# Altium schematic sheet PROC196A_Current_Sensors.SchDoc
size 431 x 279 mm; Date: Not shown in title block; ApprovedBy: Not shown in title block; CheckedBy: Not shown in title block; Author: Not shown in title block; CompanyName: Not shown in title block; Engineer: Not shown in title block; Organization: Not shown in title block; Address1: Not shown in title block; Address2: Not shown in title block; Address3: Not shown in title block; Address4: Not shown in title block; DocumentNumber: 23; Revision: Use project parameter SCH_Rev; SheetNumber: 23; SheetTotal: 25; PageSetup: Record=PageOptions¦CenterHorizontal=True¦CenterVertical=True¦PrintScale=1.00¦XCorrection=1.00¦YCorrection=1.00¦PrintKind=0¦BorderSize=5000000¦LeftOffset=0¦BottomOffset=0¦Orientation=2¦PaperLength=1000¦PaperWidth=1000¦Scale=100¦PaperSource=15¦PrintQuality=600¦MediaType=1¦DitherType=10¦PaperKind=Letter¦PrintScaleMode=1
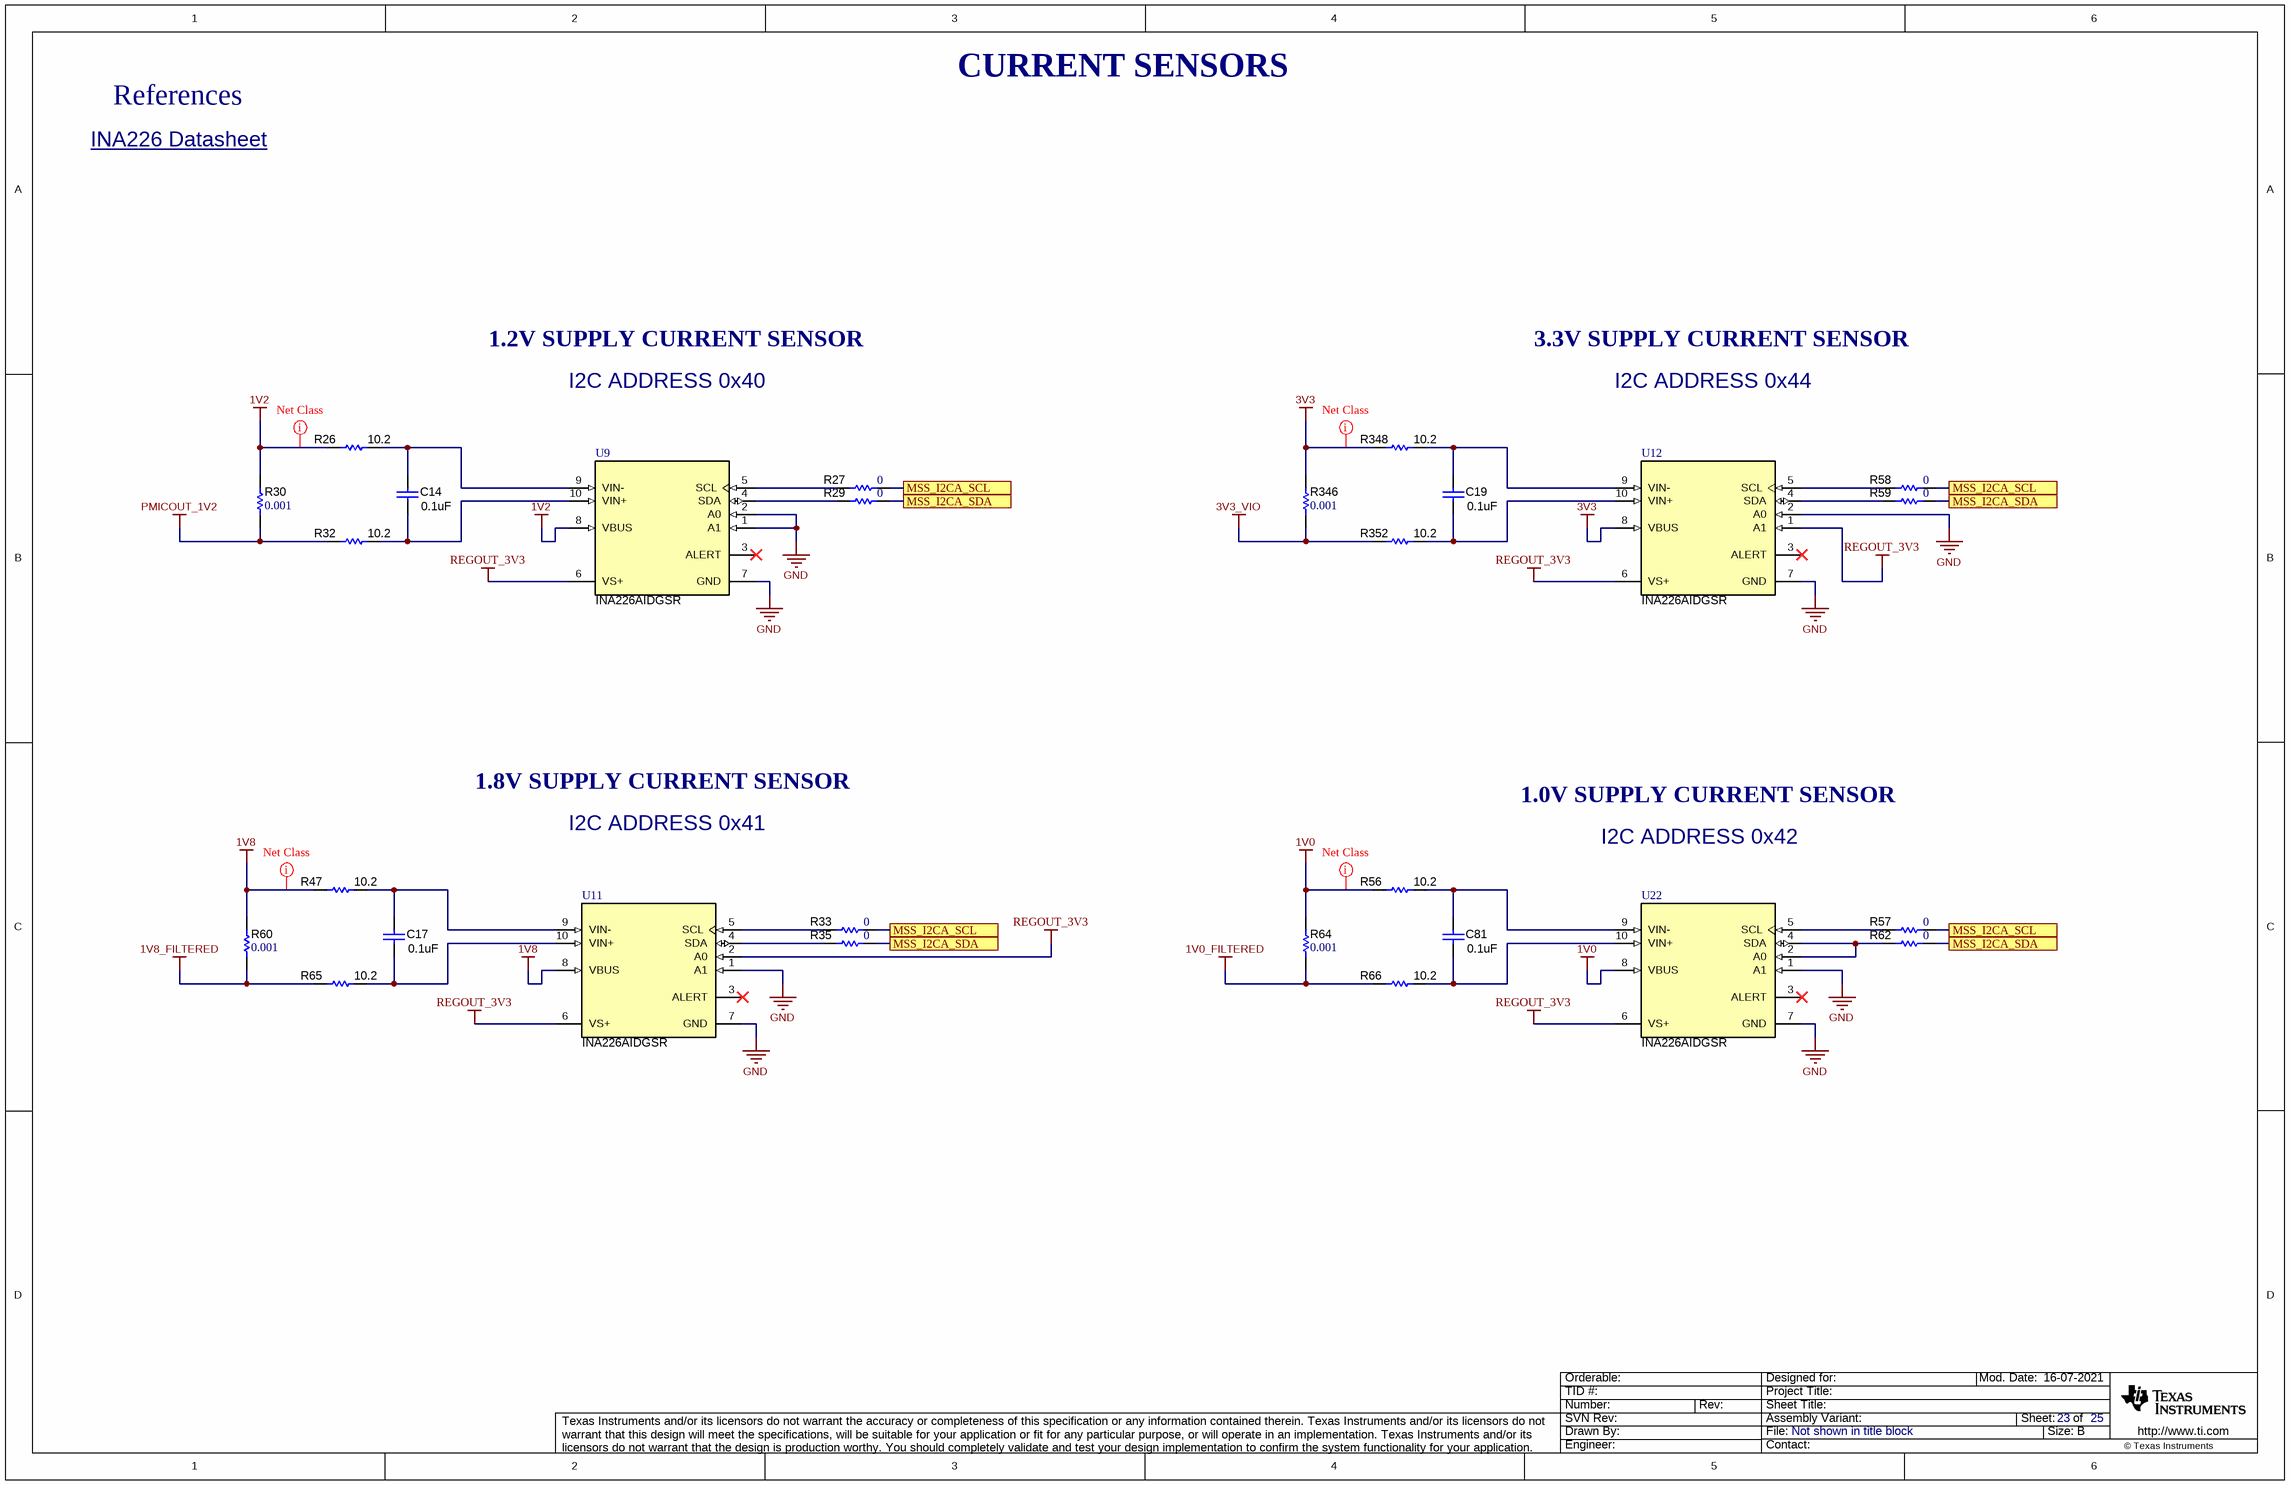
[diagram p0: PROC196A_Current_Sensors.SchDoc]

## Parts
C14  ValueDisplayed: 0.1uF  [0402L]  (hidden comment: GCM155R71A104KA55D)
C17  ValueDisplayed: 0.1uF  [0402L]  (hidden comment: GCM155R71A104KA55D)
C19  ValueDisplayed: 0.1uF  [0402L]  (hidden comment: GCM155R71A104KA55D)
C81  ValueDisplayed: 0.1uF  [0402L]  (hidden comment: GCM155R71A104KA55D)
R26  ValueDisplayed: 10.2  [0402L]  (hidden comment: CRCW040210R2FKED)
R27  ValueDisplayed: 0  [0402L]  (hidden comment: ERJ-2GE0R00X)
R29  ValueDisplayed: 0  [0402L]  (hidden comment: ERJ-2GE0R00X)
R30  ValueDisplayed: 0.001  [1206L]  (hidden comment: CSNL1206FT1L00)
R32  ValueDisplayed: 10.2  [0402L]  (hidden comment: CRCW040210R2FKED)
R33  ValueDisplayed: 0  [0402L]  (hidden comment: ERJ-2GE0R00X)
R35  ValueDisplayed: 0  [0402L]  (hidden comment: ERJ-2GE0R00X)
R47  ValueDisplayed: 10.2  [0402L]  (hidden comment: CRCW040210R2FKED)
R56  ValueDisplayed: 10.2  [0402L]  (hidden comment: CRCW040210R2FKED)
R57  ValueDisplayed: 0  [0402L]  (hidden comment: ERJ-2GE0R00X)
R58  ValueDisplayed: 0  [0402L]  (hidden comment: ERJ-2GE0R00X)
R59  ValueDisplayed: 0  [0402L]  (hidden comment: ERJ-2GE0R00X)
R60  ValueDisplayed: 0.001  [1206L]  (hidden comment: CSNL1206FT1L00)
R62  ValueDisplayed: 0  [0402L]  (hidden comment: ERJ-2GE0R00X)
R64  ValueDisplayed: 0.001  [1206L]  (hidden comment: CSNL1206FT1L00)
R65  ValueDisplayed: 10.2  [0402L]  (hidden comment: CRCW040210R2FKED)
R66  ValueDisplayed: 10.2  [0402L]  (hidden comment: CRCW040210R2FKED)
R346  ValueDisplayed: 0.001  [1206L]  (hidden comment: CSNL1206FT1L00)
R348  ValueDisplayed: 10.2  [0402L]  (hidden comment: CRCW040210R2FKED)
R352  ValueDisplayed: 10.2  [0402L]  (hidden comment: CRCW040210R2FKED)
U9  INA226AIDGSR  [DGS0010A_L]
U11  INA226AIDGSR  [DGS0010A_L]
U12  INA226AIDGSR  [DGS0010A_L]
U22  INA226AIDGSR  [DGS0010A_L]

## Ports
MSS_I2CA_SCL, MSS_I2CA_SDA

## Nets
1V0: R56.1 R64.2 U22.8(VBUS)
1V0_FILTERED: R64.1 R66.1
1V2: R26.1 R30.2 U9.8(VBUS)
1V8: R47.1 R60.2 U11.8(VBUS)
1V8_FILTERED: R60.1 R65.1
3V3: R346.2 R348.1 U12.8(VBUS)
3V3_VIO: R346.1 R352.1
GND: U9.1(A1) U9.2(A0) U9.7(GND) U11.1(A1) U11.7(GND) U12.2(A0) U12.7(GND) U22.1(A1) U22.7(GND)
PMICOUT_1V2: R30.1 R32.1
REGOUT_3V3: U9.6(VS+) U11.2(A0) U11.6(VS+) U12.1(A1) U12.6(VS+) U22.6(VS+)
MSS_I2CA_SCL: R27.2 R33.2 R57.2 R58.2 ; port MSS_I2CA_SCL
MSS_I2CA_SDA: R29.2 R35.2 R59.2 R62.2 ; port MSS_I2CA_SDA
NetC14_1: C14.1 R26.2 U9.9(VIN-)
NetC14_2: C14.2 R32.2 U9.10(VIN+)
NetC17_1: C17.1 R47.2 U11.9(VIN-)
NetC17_2: C17.2 R65.2 U11.10(VIN+)
NetC19_1: C19.1 R348.2 U12.9(VIN-)
NetC19_2: C19.2 R352.2 U12.10(VIN+)
NetC81_1: C81.1 R56.2 U22.9(VIN-)
NetC81_2: C81.2 R66.2 U22.10(VIN+)
NetR27_1: R27.1 U9.5(SCL)
NetR29_1: R29.1 U9.4(SDA)
NetR33_1: R33.1 U11.5(SCL)
NetR35_1: R35.1 U11.4(SDA)
NetR57_1: R57.1 U22.5(SCL)
NetR58_1: R58.1 U12.5(SCL)
NetR59_1: R59.1 U12.4(SDA)
NetR62_1: R62.1 U22.2(A0) U22.4(SDA)

Not connected (* = marked no-connect by the designer): U9 3(ALERT)*; U11 3(ALERT)*; U12 3(ALERT)*; U22 3(ALERT)*

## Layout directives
net class PWR: 1V0, 1V2, 1V8, 3V3

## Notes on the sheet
- CURRENT SENSORS
- References
- INA226 Datasheet <http://www.ti.com/lit/ds/symlink/ina226.pdf>
- 1.2V SUPPLY CURRENT SENSOR
- 3.3V SUPPLY CURRENT SENSOR
- I2C ADDRESS 0x40
- I2C ADDRESS 0x44
- 1.8V SUPPLY CURRENT SENSOR
- I2C ADDRESS 0x41
- 1.0V SUPPLY CURRENT SENSOR
- I2C ADDRESS 0x42

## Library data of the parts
C14 C17 C19 C81 = CMP-0006350-2: CAP, CERM, 0.1 uF, 10 V, +/- 10%, X7R, AEC-Q200 Grade 1, 0402; Manufacturer: MuRata; TaMin_C: -55°C; Polarized: N; SizeAreaWB_mm2: 3; Value1: Unknown; U/M: EA; Value: 0.1uF; TaMax_C: 125°C; SizeZ_mm: 0.6; SizeX_mm: 1; SizeY_mm: 0.5; Cap_Case: 0402; Value2: 10V; AEC Qualified: Y; Cap_F: 100nF; AEC Category: Q200
R26 R32 R47 R56 R65 R66 R348 R352 = CMP-0025964-3: RES, 10.2, 1%, 0.063 W, AEC-Q200 Grade 0, 0402; Manufacturer: Vishay-Dale; Power_W: 63mW; TempCo: 100 ppm/C; Value_Code: 10R2; Value: 10.2; EIA_Code: E96; SizeX_mm: 1; SizeY_mm: 0.5; SizeZ_mm: 0.6; Value2: 0.063W; AEC Qualified: Y; VDC_V: 50V; AEC Category: Q200; AEC Grade: 0
R27 R29 R33 R35 R57-R59 R62 = CMP-0026992-3: RES, 0, 5%, 0.1 W, AEC-Q200 Grade 0, 0402; Manufacturer: Panasonic; Power_W: 100mW; TempCo: 600 ppm/C; Value_Code: 0000; Value: 0; EIA_Code: E24; SizeX_mm: 1; SizeY_mm: 0.5; SizeZ_mm: 0.6; Value2: 0.1W; AEC Qualified: Y; VDC_V: 50V; AEC Category: Q200; SizeAreaWB_mm2: 3
R30 R60 R64 R346 = CMP-0017253-2: RES, 0.001, 1%, 1 W, AEC-Q200 Grade 0, 1206; Manufacturer: Stackpole Electronics Inc; Power_W: 1W; TempCo: 50 ppm/C; Value_Code: 1L000; U/M: EA; Value: 0.001; EIA_Code: E96; Res_ohm: 1m; SizeX_mm: 3.2; SizeY_mm: 1.6; SizeZ_mm: 1.35; SizeArea_mm2: 5.12; AEC Qualified: Y; AEC Grade: 0; AEC Category: Q200
U9 U11 U12 U22 = CMP-0037979-1: High-Side Measurement, Bi-Directional Current / Power Monitor with I2C Interface, 2.7 to 5.5 V, -40 to 125 degC, 10-pin SOP (DGS10), Green (RoHS & no Sb/Br); Manufacturer: Texas Instruments; Common Mode Range(Max)(V): 36; Vs(Min)(V): 2.7; SubFamily: Current Shunt Monitor; Small-Signal Bandwidth(Typ)(MHz): 0.007; CMRR(Min)(dB): 126; Gain(V/V): 1; Vs(Max)(V): 5.5; Rating: Catalog; Input Offset Drift (+/-)(Max)(uV/Degrees Celsius): 0.1; Quiescent Current (+/-)(Typ)(mA): 0.33; Common Mode Range(Min)(V): 0; Input Offset (+/-)(Max)(uV): 10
